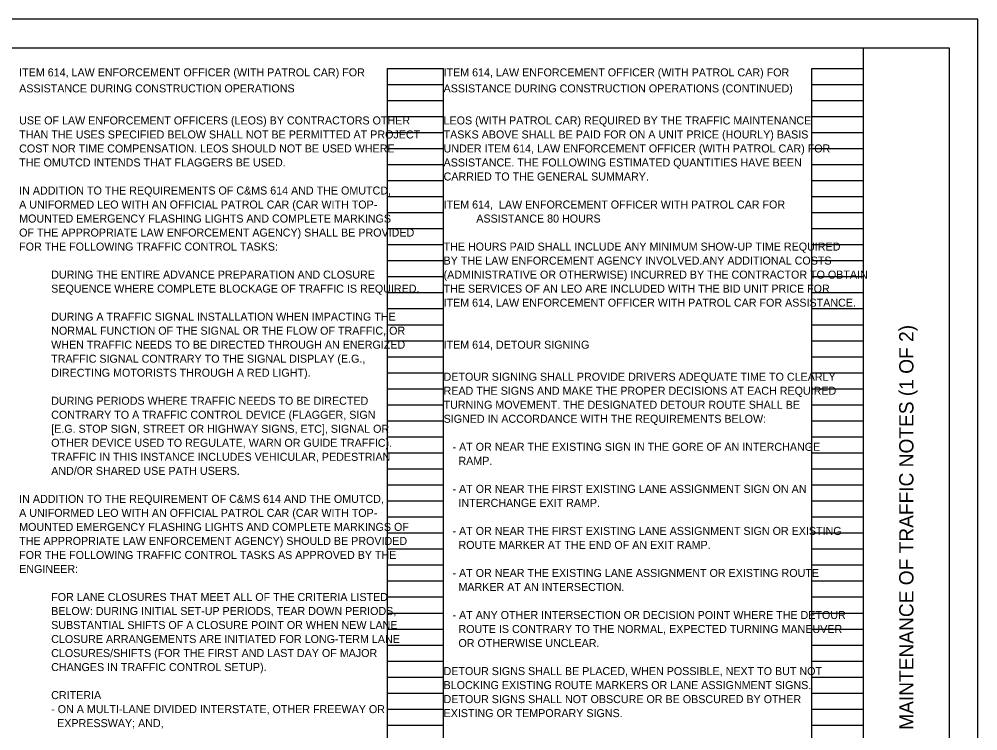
# Model space of a CAD drawing. Extents: x -11.6 to 64.7, y 0 to 22.
# Drawn here: x 17.24 to 34, y 9.56 to 22 of the extents above; entities that cross this region are included whole.
import ezdxf

# ---------------------------------------------------------------- set-up
doc = ezdxf.new("R2010")
doc.units = 0
for name, color, linetype in [('SH_Border', 7, 'Continuous'), ('SH_Cut_Line', 7, 'Continuous'), ('SH_Data', 7, 'Continuous'), ('SH_Text', 7, 'Continuous')]:
    doc.layers.add(name, color=color, linetype=linetype)

msp = doc.modelspace()

# ---------------------------------------------------------------- linework, layer by layer
at = {"layer": 'SH_Border'}
msp.add_line((32, 0.5), (32, 21.5), dxfattribs=at)
msp.add_lwpolyline([(1.5, 21.5), (33.5, 21.5), (33.5, 0.5), (1.5, 0.5)], close=True, dxfattribs=at)
at = {"layer": 'SH_Cut_Line'}
msp.add_lwpolyline([(0, 0), (34, 0), (34, 22), (0, 22)], close=True, dxfattribs=at)
at = {"layer": 'SH_Data'}
for p, q in [((23.68, 0.98), (23.68, 21.14)), ((23.68, 21.14), (24.66, 21.14)), ((24.66, 0.98), (24.66, 21.14)), ((31.1, 0.98), (31.1, 21.14)), ((31.1, 21.14), (32, 21.14)), ((32, 0.98), (32, 21.14)), ((23.68, 20.86), (24.66, 20.86)), ((31.1, 20.86), (32, 20.86)), ((23.68, 20.58), (24.66, 20.58)), ((31.1, 20.58), (32, 20.58)), ((23.68, 20.3), (24.66, 20.3)), ((31.1, 20.3), (32, 20.3)), ((23.68, 20.02), (24.66, 20.02)), ((31.1, 20.02), (32, 20.02)), ((23.68, 19.74), (24.66, 19.74)), ((31.1, 19.74), (32, 19.74)), ((23.68, 19.46), (24.66, 19.46)), ((31.1, 19.46), (32, 19.46)), ((23.68, 19.18), (24.66, 19.18)), ((31.1, 19.18), (32, 19.18)), ((23.68, 18.9), (24.66, 18.9)), ((31.1, 18.9), (32, 18.9)), ((23.68, 18.62), (24.66, 18.62)), ((31.1, 18.62), (32, 18.62)), ((23.68, 18.34), (24.66, 18.34)), ((31.1, 18.34), (32, 18.34)), ((23.68, 18.06), (24.66, 18.06)), ((31.1, 18.06), (32, 18.06)), ((23.68, 17.78), (24.66, 17.78)), ((31.1, 17.78), (32, 17.78)), ((23.68, 17.5), (24.66, 17.5)), ((31.1, 17.5), (32, 17.5)), ((23.68, 17.22), (24.66, 17.22)), ((31.1, 17.22), (32, 17.22)), ((23.68, 16.94), (24.66, 16.94)), ((31.1, 16.94), (32, 16.94)), ((23.68, 16.66), (24.66, 16.66)), ((31.1, 16.66), (32, 16.66)), ((23.68, 16.38), (24.66, 16.38)), ((31.1, 16.38), (32, 16.38)), ((23.68, 16.1), (24.66, 16.1)), ((31.1, 16.1), (32, 16.1)), ((23.68, 15.82), (24.66, 15.82)), ((31.1, 15.82), (32, 15.82)), ((23.68, 15.54), (24.66, 15.54)), ((31.1, 15.54), (32, 15.54)), ((23.68, 15.26), (24.66, 15.26)), ((31.1, 15.26), (32, 15.26)), ((23.68, 14.98), (24.66, 14.98)), ((31.1, 14.98), (32, 14.98)), ((23.68, 14.7), (24.66, 14.7)), ((31.1, 14.7), (32, 14.7)), ((23.68, 14.42), (24.66, 14.42)), ((31.1, 14.42), (32, 14.42)), ((23.68, 14.14), (24.66, 14.14)), ((31.1, 14.14), (32, 14.14)), ((23.68, 13.86), (24.66, 13.86)), ((31.1, 13.86), (32, 13.86)), ((23.68, 13.58), (24.66, 13.58)), ((31.1, 13.58), (32, 13.58)), ((23.68, 13.3), (24.66, 13.3)), ((31.1, 13.3), (32, 13.3)), ((23.68, 13.02), (24.66, 13.02)), ((31.1, 13.02), (32, 13.02)), ((23.68, 12.74), (24.66, 12.74)), ((31.1, 12.74), (32, 12.74)), ((23.68, 12.46), (24.66, 12.46)), ((31.1, 12.46), (32, 12.46)), ((23.68, 12.18), (24.66, 12.18)), ((31.1, 12.18), (32, 12.18)), ((23.68, 11.9), (24.66, 11.9)), ((31.1, 11.9), (32, 11.9)), ((23.68, 11.62), (24.66, 11.62)), ((31.1, 11.62), (32, 11.62)), ((23.68, 11.34), (24.66, 11.34)), ((31.1, 11.34), (32, 11.34)), ((23.68, 11.06), (24.66, 11.06)), ((31.1, 11.06), (32, 11.06)), ((23.68, 10.78), (24.66, 10.78)), ((31.1, 10.78), (32, 10.78)), ((23.68, 10.5), (24.66, 10.5)), ((31.1, 10.5), (32, 10.5)), ((23.68, 10.22), (24.66, 10.22)), ((31.1, 10.22), (32, 10.22)), ((23.68, 9.94), (24.66, 9.94)), ((31.1, 9.94), (32, 9.94)), ((23.68, 9.66), (24.66, 9.66)), ((31.1, 9.66), (32, 9.66))]:
    msp.add_line(p, q, dxfattribs=at)

# ---------------------------------------------------------------- texts
msp.add_text('MAINTENANCE OF TRAFFIC NOTES (1 OF 2)', height=0.25, rotation=90, dxfattribs=at).set_placement((32.875, 9.579))
at = {"layer": 'SH_Text'}
for s, p in [('ITEM 614, LAW ENFORCEMENT OFFICER (WITH PATROL CAR) FOR', (17.24, 21)), ('ITEM 614, LAW ENFORCEMENT OFFICER (WITH PATROL CAR) FOR', (24.66, 21)), ('ASSISTANCE DURING CONSTRUCTION OPERATIONS', (17.24, 20.72)), ('ASSISTANCE DURING CONSTRUCTION OPERATIONS (CONTINUED)', (24.66, 20.72)), ('USE OF LAW ENFORCEMENT OFFICERS (LEOS) BY CONTRACTORS OTHER ', (17.24, 20.16)), ('LEOS (WITH PATROL CAR) REQUIRED BY THE TRAFFIC MAINTENANCE ', (24.66, 20.16)), ('THAN THE USES SPECIFIED BELOW SHALL NOT BE PERMITTED AT PROJECT ', (17.24, 19.915)), ('TASKS ABOVE SHALL BE PAID FOR ON A UNIT PRICE (HOURLY) BASIS ', (24.66, 19.915)), ('COST NOR TIME COMPENSATION. LEOS SHOULD NOT BE USED WHERE ', (17.24, 19.67)), ('UNDER ITEM 614, LAW ENFORCEMENT OFFICER (WITH PATROL CAR) FOR', (24.66, 19.67)), ('THE OMUTCD INTENDS THAT FLAGGERS BE USED.', (17.24, 19.425)), ('ASSISTANCE. THE FOLLOWING ESTIMATED QUANTITIES HAVE BEEN ', (24.66, 19.425)), ('CARRIED TO THE GENERAL SUMMARY.', (24.66, 19.18)), ('IN ADDITION TO THE REQUIREMENTS OF C&MS 614 AND THE OMUTCD, ', (17.24, 18.935)), ('A UNIFORMED LEO WITH AN OFFICIAL PATROL CAR (CAR WITH TOP-', (17.24, 18.69)), ('ITEM 614,  LAW ENFORCEMENT OFFICER WITH PATROL CAR FOR', (24.66, 18.69)), ('MOUNTED EMERGENCY FLASHING LIGHTS AND COMPLETE MARKINGS ', (17.24, 18.445)), ('           ASSISTANCE 80 HOURS', (24.66, 18.445)), ('OF THE APPROPRIATE LAW ENFORCEMENT AGENCY) SHALL BE PROVIDED ', (17.24, 18.2)), ('FOR THE FOLLOWING TRAFFIC CONTROL TASKS:', (17.24, 17.955)), ('THE HOURS PAID SHALL INCLUDE ANY MINIMUM SHOW-UP TIME REQUIRED', (24.66, 17.955)), ('BY THE LAW ENFORCEMENT AGENCY INVOLVED.ANY ADDITIONAL COSTS', (24.66, 17.71)), ('DURING THE ENTIRE ADVANCE PREPARATION AND CLOSURE ', (17.8, 17.465)), ('(ADMINISTRATIVE OR OTHERWISE) INCURRED BY THE CONTRACTOR TO OBTAIN', (24.66, 17.465)), ('SEQUENCE WHERE COMPLETE BLOCKAGE OF TRAFFIC IS REQUIRED.', (17.8, 17.22)), ('THE SERVICES OF AN LEO ARE INCLUDED WITH THE BID UNIT PRICE FOR', (24.66, 17.22)), ('ITEM 614, LAW ENFORCEMENT OFFICER WITH PATROL CAR FOR ASSISTANCE.', (24.66, 16.975)), ('DURING A TRAFFIC SIGNAL INSTALLATION WHEN IMPACTING THE ', (17.8, 16.73)), ('NORMAL FUNCTION OF THE SIGNAL OR THE FLOW OF TRAFFIC, OR ', (17.8, 16.485)), ('WHEN TRAFFIC NEEDS TO BE DIRECTED THROUGH AN ENERGIZED ', (17.8, 16.24)), ('ITEM 614, DETOUR SIGNING', (24.66, 16.24)), ('TRAFFIC SIGNAL CONTRARY TO THE SIGNAL DISPLAY (E.G., ', (17.8, 15.995)), ('DIRECTING MOTORISTS THROUGH A RED LIGHT).', (17.8, 15.75)), ('DETOUR SIGNING SHALL PROVIDE DRIVERS ADEQUATE TIME TO CLEARLY', (24.66, 15.68)), ('READ THE SIGNS AND MAKE THE PROPER DECISIONS AT EACH REQUIRED', (24.66, 15.435)), ('DURING PERIODS WHERE TRAFFIC NEEDS TO BE DIRECTED ', (17.8, 15.26)), ('TURNING MOVEMENT. THE DESIGNATED DETOUR ROUTE SHALL BE ', (24.66, 15.19)), ('CONTRARY TO A TRAFFIC CONTROL DEVICE (FLAGGER, SIGN ', (17.8, 15.015)), ('SIGNED IN ACCORDANCE WITH THE REQUIREMENTS BELOW:', (24.66, 14.945)), ('[E.G. STOP SIGN, STREET OR HIGHWAY SIGNS, ETC], SIGNAL OR ', (17.8, 14.77)), ('OTHER DEVICE USED TO REGULATE, WARN OR GUIDE TRAFFIC). ', (17.8, 14.525)), ('   - AT OR NEAR THE EXISTING SIGN IN THE GORE OF AN INTERCHANGE ', (24.66, 14.455)), ('TRAFFIC IN THIS INSTANCE INCLUDES VEHICULAR, PEDESTRIAN ', (17.8, 14.28)), ('     RAMP.', (24.66, 14.21)), ('AND/OR SHARED USE PATH USERS.', (17.8, 14.035)), ('   - AT OR NEAR THE FIRST EXISTING LANE ASSIGNMENT SIGN ON AN', (24.66, 13.72)), ('IN ADDITION TO THE REQUIREMENT OF C&MS 614 AND THE OMUTCD,', (17.24, 13.545)), ('     INTERCHANGE EXIT RAMP.', (24.66, 13.475)), ('A UNIFORMED LEO WITH AN OFFICIAL PATROL CAR (CAR WITH TOP-', (17.24, 13.3)), ('MOUNTED EMERGENCY FLASHING LIGHTS AND COMPLETE MARKINGS OF', (17.24, 13.055)), ('   - AT OR NEAR THE FIRST EXISTING LANE ASSIGNMENT SIGN OR EXISTING ', (24.66, 12.985)), ('THE APPROPRIATE LAW ENFORCEMENT AGENCY) SHOULD BE PROVIDED', (17.24, 12.81)), ('     ROUTE MARKER AT THE END OF AN EXIT RAMP.', (24.66, 12.74)), ('FOR THE FOLLOWING TRAFFIC CONTROL TASKS AS APPROVED BY THE ', (17.24, 12.565)), ('ENGINEER:', (17.24, 12.32)), ('   - AT OR NEAR THE EXISTING LANE ASSIGNMENT OR EXISTING ROUTE ', (24.66, 12.25)), ('     MARKER AT AN INTERSECTION.', (24.66, 12.005)), ('FOR LANE CLOSURES THAT MEET ALL OF THE CRITERIA LISTED ', (17.8, 11.83)), ('BELOW: DURING INITIAL SET-UP PERIODS, TEAR DOWN PERIODS,', (17.8, 11.585)), ('   - AT ANY OTHER INTERSECTION OR DECISION POINT WHERE THE DETOUR', (24.66, 11.515)), ('SUBSTANTIAL SHIFTS OF A CLOSURE POINT OR WHEN NEW LANE ', (17.8, 11.34)), ('     ROUTE IS CONTRARY TO THE NORMAL, EXPECTED TURNING MANEUVER', (24.66, 11.27)), ('CLOSURE ARRANGEMENTS ARE INITIATED FOR LONG-TERM LANE', (17.8, 11.095)), ('     OR OTHERWISE UNCLEAR.', (24.66, 11.025)), ('CLOSURES/SHIFTS (FOR THE FIRST AND LAST DAY OF MAJOR', (17.8, 10.85)), ('CHANGES IN TRAFFIC CONTROL SETUP).', (17.8, 10.605)), ('DETOUR SIGNS SHALL BE PLACED, WHEN POSSIBLE, NEXT TO BUT NOT ', (24.66, 10.535)), ('BLOCKING EXISTING ROUTE MARKERS OR LANE ASSIGNMENT SIGNS. ', (24.66, 10.29)), ('CRITERIA', (17.8, 10.115)), ('DETOUR SIGNS SHALL NOT OBSCURE OR BE OBSCURED BY OTHER ', (24.66, 10.045)), ('- ON A MULTI-LANE DIVIDED INTERSTATE, OTHER FREEWAY OR ', (17.8, 9.87)), ('EXISTING OR TEMPORARY SIGNS.', (24.66, 9.8)), ('  EXPRESSWAY; AND,', (17.8, 9.625))]:
    msp.add_text(s, height=0.14, dxfattribs=at).set_placement(p)

doc.saveas('drawing.dxf')
